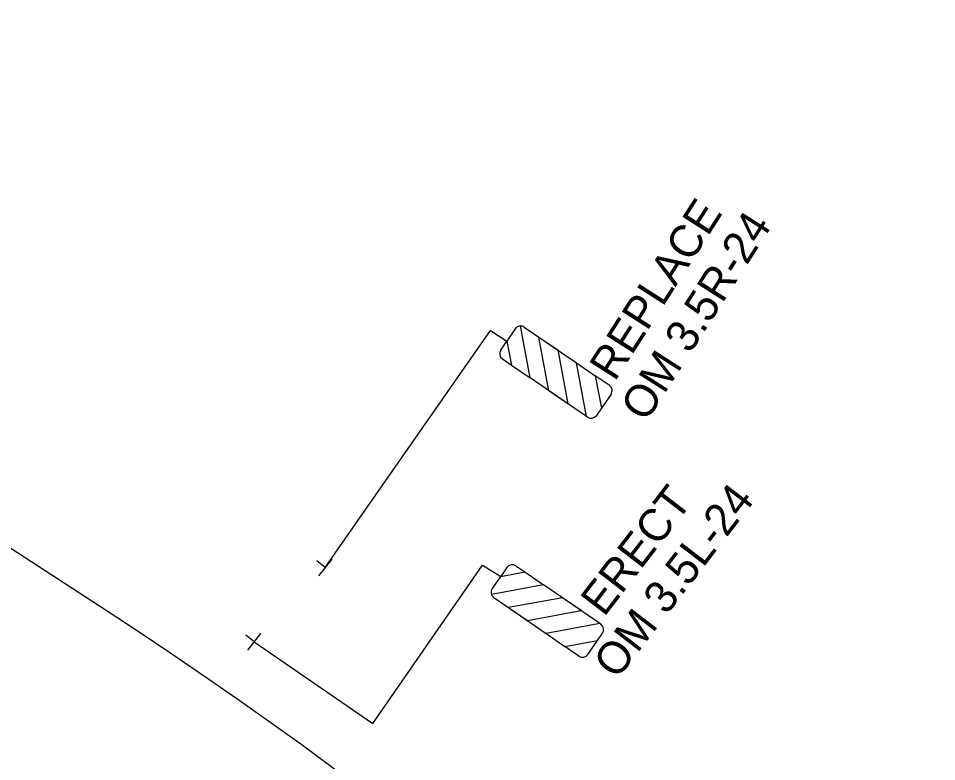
# Model space of a CAD drawing. Extents: x 2001876 to 2025694, y 804561 to 868938.
# Drawn here: x 2022302 to 2022872, y 814380 to 814841 of the extents above; entities that cross this region are included whole.
import ezdxf

# ---------------------------------------------------------------- set-up
doc = ezdxf.new("R2010")
doc.units = 0
for name, color, linetype in [('RD_PD_CLEAR ZONE', 7, 'Continuous'), ('TR SN EXTRUDED PANEL SIGNS - GROUND MOUNTED', 7, 'Continuous'), ('TR SN EXTRUDED PANEL SIGNS- MOUNTED OVERHEAD', 7, 'Continuous'), ('TR SN FLAT SHEET - TYPE III - FIXED SZ and MSG SIGN', 7, 'Continuous')]:
    doc.layers.add(name, color=color, linetype=linetype)

msp = doc.modelspace()

# ---------------------------------------------------------------- linework, layer by layer
at = {"layer": 'RD_PD_CLEAR ZONE'}
msp.add_line((2022356.17, 814473.42), (2021574.32, 814981.91), dxfattribs=at)
msp.add_arc((2020794.27, 812071.86), 2864.79, 355.71297, 56.96135, dxfattribs=at)
at = {"layer": 'TR SN EXTRUDED PANEL SIGNS- MOUNTED OVERHEAD'}
for p, q in [((2022492.18, 814500.26), (2022594.77, 814647.44)), ((2022594.77, 814647.44), (2022604.86, 814640.85))]:
    msp.add_line(p, q, dxfattribs=at)
msp.add_lwpolyline([(2022448.01, 814453.99), (2022521.67, 814403.29), (2022589.71, 814501.57), (2022601.1, 814494.72)], dxfattribs=at)
at = {"layer": 'TR SN FLAT SHEET - TYPE III - FIXED SZ and MSG SIGN'}
for p, q in [((2022610.08, 814648.48), (2022604.86, 814640.85)), ((2022619.34, 814617.91), (2022613.28, 814650.22)), ((2022615.64, 814649.52), (2022648.1, 814627.31)), ((2022601.05, 814635.27), (2022604.86, 814640.85)), ((2022604.86, 814640.85), (2022607.67, 814625.9)), ((2022602.09, 814629.71), (2022607.67, 814625.9)), ((2022607.67, 814625.9), (2022619.34, 814617.91)), ((2022654.35, 814593.95), (2022648.1, 814627.31)), ((2022648.1, 814627.31), (2022659.77, 814619.33)), ((2022654.35, 814593.95), (2022619.34, 814617.91)), ((2022668.46, 814613.38), (2022659.77, 814619.33)), ((2022659.77, 814619.33), (2022663.56, 814599.13)), ((2022669.5, 814607.82), (2022663.56, 814599.13)), ((2022663.56, 814599.13), (2022660.47, 814594.61)), ((2022654.91, 814593.57), (2022654.35, 814593.95)), ((2022492.18, 814500.26), (2022486.94, 814504.37)), ((2022496.21, 814505.41), (2022488.05, 814495.01)), ((2022604.93, 814500.28), (2022601.1, 814494.72)), ((2022610.49, 814501.31), (2022616.06, 814497.48)), ((2022595.86, 814487.1), (2022601.1, 814494.72)), ((2022601.1, 814494.72), (2022616.06, 814497.48)), ((2022616.06, 814497.48), (2022627.71, 814489.46)), ((2022627.71, 814489.46), (2022595.38, 814483.49)), ((2022662.65, 814465.4), (2022627.71, 814489.46)), ((2022596.88, 814481.54), (2022629.28, 814459.24)), ((2022662.65, 814465.4), (2022629.28, 814459.24)), ((2022663.21, 814465.02), (2022662.65, 814465.4)), ((2022448.06, 814454.05), (2022442.82, 814458.15)), ((2022452.09, 814459.19), (2022443.93, 814448.79)), ((2022629.28, 814459.24), (2022640.93, 814451.22)), ((2022640.93, 814451.22), (2022661.14, 814454.96)), ((2022655.16, 814446.28), (2022661.14, 814454.96)), ((2022661.14, 814454.96), (2022664.24, 814459.46)), ((2022649.6, 814445.25), (2022640.93, 814451.22))]:
    msp.add_line(p, q, dxfattribs=at)
for points in [[(2022642.68, 814601.94), (2022631.01, 814609.92), (2022624.75, 814643.28), (2022636.43, 814635.3)], [(2022651, 814473.42), (2022639.36, 814481.44), (2022605.98, 814475.28), (2022617.63, 814467.26)]]:
    msp.add_lwpolyline(points, close=True, dxfattribs=at)
for centre, start, end in [((2022613.38, 814646.22), 91.4751, 145.6194), ((2022613.38, 814646.22), 55.6194, 91.475), ((2022604.35, 814633.01), 145.6194, 235.6194), ((2022666.2, 814610.08), 325.6194, 55.6194), ((2022657.17, 814596.87), 235.6194, 325.6194), ((2022608.22, 814498.01), 55.4595, 145.4595), ((2022599.15, 814484.84), 145.4595, 199.6038), ((2022599.15, 814484.84), 199.6038, 235.4595), ((2022660.94, 814461.73), 325.4595, 55.4595), ((2022651.87, 814448.55), 235.4595, 325.4595)]:
    msp.add_arc(centre, 4, start, end, dxfattribs=at)

# ---------------------------------------------------------------- texts
at = {"layer": 'TR SN EXTRUDED PANEL SIGNS - GROUND MOUNTED'}
for s, rotation, p in [('REPLACE', 57.408, (2022671.87, 814615.21)), ('OM 3.5R-24', 57.408, (2022691.27, 814589.86)), ('ERECT ', 52.4557, (2022665.17, 814468.98)), ('OM 3.5L-24', 52.4557, (2022673.12, 814430.09))]:
    msp.add_text(s, height=20, rotation=rotation, dxfattribs=at).set_placement(p)

doc.saveas('drawing.dxf')
